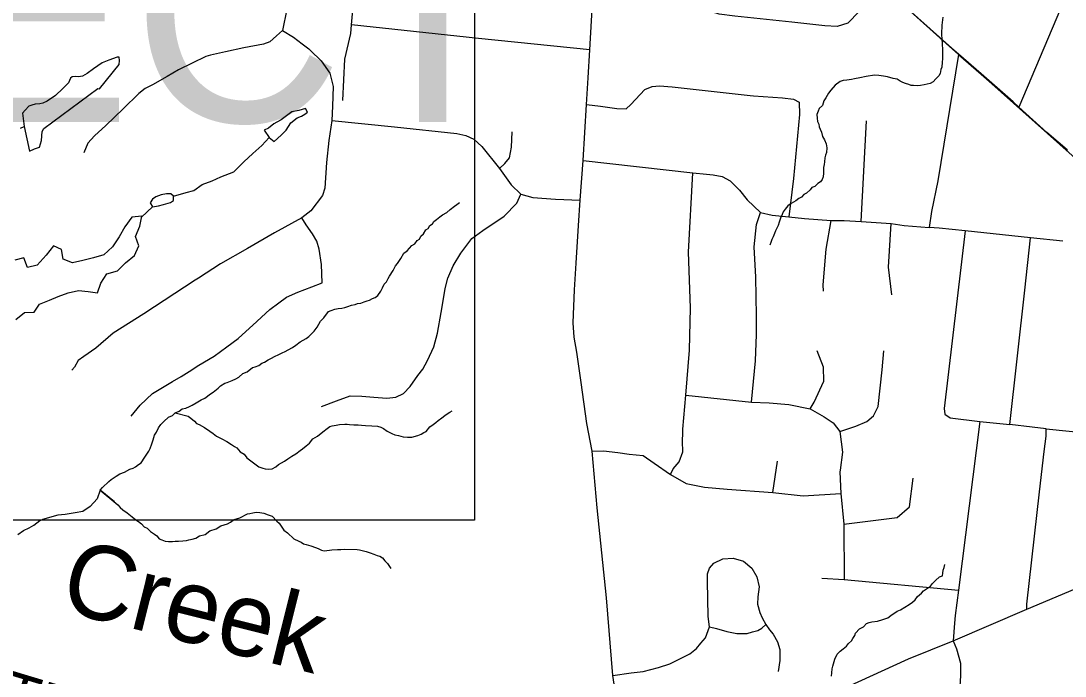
# Model space of a CAD drawing. Extents: x 0 to 34, y 0 to 22.
# Drawn here: x 6.811 to 7.478, y 14.523 to 14.941 of the extents above; entities that cross this region are included whole.
import ezdxf

# ---------------------------------------------------------------- set-up
doc = ezdxf.new("R2010")
doc.units = 0
for name, color, linetype in [('Default', 7, 'Continuous'), ('GM_X_Corporation', 7, 'Continuous'), ('GM_X_County_Road', 7, 'Continuous'), ('GM_X_County_Road_Text', 7, 'Continuous'), ('GM_X_Minor_Lake', 7, 'Continuous'), ('GM_X_Minor_River', 7, 'Continuous'), ('GM_X_Minor_River_Text', 7, 'Continuous'), ('GM_X_Rail_Line', 7, 'Continuous'), ('GM_X_State_Route', 7, 'Continuous'), ('GM_X_Township', 7, 'Continuous'), ('GM_X_Township_Road', 7, 'Continuous'), ('SH_Text', 7, 'Continuous')]:
    doc.layers.add(name, color=color, linetype=linetype)

msp = doc.modelspace()

# ---------------------------------------------------------------- linework, layer by layer
at = {"layer": 'Default'}
msp.add_lwpolyline([(5.72003, 15.05333), (7.10043, 15.05333), (7.10043, 14.62233), (5.72003, 14.62233)], close=True, dxfattribs=at)
at = {"layer": 'GM_X_Corporation'}
for points in [[(7.48543, 14.97447), (7.44826, 14.88634), (7.4662, 14.87017), (7.47922, 14.85892)], [(7.47922, 14.85892), (7.4662, 14.87017), (7.44826, 14.88634), (7.44459, 14.88965), (7.42409, 14.90759), (7.40961, 14.92024), (7.40377, 14.92534), (7.37674, 14.94955)]]:
    msp.add_lwpolyline(points, dxfattribs=at)
at = {"layer": 'GM_X_County_Road'}
for points in [[(7.16536, 14.7866), (7.16688, 14.81062), (7.16792, 14.82692), (7.16996, 14.85227), (7.17194, 14.88792), (7.17312, 14.90505), (7.17413, 14.92296), (7.17633, 14.9603), (7.17775, 14.9708), (7.17953, 14.98109), (7.1819, 14.98879), (7.1851, 15.0002), (7.19108, 15.01505), (7.20244, 15.04252)], [(7.19462, 14.47266), (7.19273, 14.49817), (7.18876, 14.52298), (7.18487, 14.57269), (7.17892, 14.63024), (7.17568, 14.66641), (7.17231, 14.68409), (7.16861, 14.71026), (7.16576, 14.7296), (7.1641, 14.73924), (7.16342, 14.74839), (7.16428, 14.76959), (7.16536, 14.7866)], [(7.19462, 14.47266), (7.20479, 14.48077), (7.21024, 14.48461), (7.21649, 14.48758), (7.22219, 14.4894), (7.24943, 14.49374), (7.26769, 14.49671), (7.30242, 14.50216), (7.31344, 14.50423), (7.32554, 14.50851), (7.34044, 14.51676), (7.3531, 14.52237), (7.37775, 14.53379), (7.4064, 14.5452), (7.45328, 14.56541), (7.48427, 14.57849), (7.58457, 14.59524), (7.64482, 14.60405), (7.73637, 14.61978), (7.74169, 14.62255)]]:
    msp.add_lwpolyline(points, dxfattribs=at)
at = {"layer": 'GM_X_Minor_Lake'}
for points in [[(6.8734, 14.91826), (6.87207, 14.91829), (6.8669, 14.9163), (6.8625, 14.91468), (6.85692, 14.9108), (6.85287, 14.90784), (6.84999, 14.906), (6.84751, 14.90567), (6.84562, 14.9059), (6.84334, 14.90575), (6.84237, 14.90482), (6.84098, 14.90181), (6.83749, 14.89827), (6.83265, 14.89381), (6.82745, 14.89011), (6.82458, 14.88884), (6.82267, 14.8885), (6.81982, 14.88818), (6.81753, 14.88765), (6.81562, 14.88693), (6.81329, 14.88432), (6.81154, 14.88245), (6.8128, 14.87393)], [(6.8128, 14.87393), (6.81619, 14.85823), (6.81925, 14.85968), (6.8225, 14.86076), (6.82372, 14.86492), (6.82422, 14.8708), (6.82521, 14.87268), (6.85971, 14.89821), (6.86084, 14.89799), (6.87349, 14.91351), (6.87354, 14.91617), (6.8734, 14.91826)], [(6.90809, 14.8294), (6.9163, 14.83171), (6.92107, 14.83294), (6.92647, 14.83682), (6.93278, 14.83917), (6.93834, 14.84172), (6.94676, 14.84497), (6.95296, 14.85131), (6.95876, 14.8567), (6.96456, 14.86171), (6.96922, 14.86694)], [(6.89466, 14.82264), (6.89847, 14.82332), (6.90172, 14.82402), (6.90611, 14.82526), (6.90803, 14.82655), (6.90809, 14.8294), (6.90641, 14.83096), (6.90375, 14.83082), (6.90032, 14.83032), (6.89688, 14.82906), (6.89476, 14.82739), (6.89319, 14.82514)], [(6.88775, 14.81594), (6.89466, 14.82264)], [(6.89319, 14.82514), (6.89467, 14.82264)], [(6.8074, 14.75066), (6.81281, 14.75511), (6.81908, 14.75537), (6.82241, 14.76043), (6.82891, 14.76296), (6.83447, 14.76532), (6.84078, 14.76766), (6.84745, 14.76905), (6.85352, 14.76855), (6.85958, 14.76767), (6.8616, 14.7739), (6.86552, 14.77971), (6.87239, 14.78166), (6.87743, 14.78669), (6.88322, 14.79152), (6.886, 14.79773), (6.88384, 14.80366), (6.88663, 14.81026), (6.8879, 14.8167), (6.88143, 14.81607), (6.87693, 14.8097), (6.87339, 14.8035), (6.86909, 14.79693), (6.86367, 14.79191), (6.85698, 14.78995), (6.85012, 14.78838), (6.84363, 14.7868), (6.8376, 14.7892), (6.83658, 14.7953), (6.8315, 14.79768), (6.82683, 14.7917), (6.821, 14.78535), (6.8149, 14.78376), (6.81255, 14.79008), (6.80682, 14.78849)]]:
    msp.add_lwpolyline(points, dxfattribs=at)
at = {"layer": 'GM_X_Minor_River'}
for points in [[(7.39965, 14.94389), (7.39899, 14.93877), (7.3989, 14.93307), (7.39902, 14.92926), (7.39937, 14.92736), (7.39948, 14.92222), (7.39944, 14.92032), (7.39958, 14.91709), (7.39935, 14.915), (7.39911, 14.91177), (7.39851, 14.91026), (7.3979, 14.9078), (7.39712, 14.90629), (7.39518, 14.90443), (7.39344, 14.90237), (7.39152, 14.90145), (7.38961, 14.90091), (7.38771, 14.90057), (7.38542, 14.90004), (7.3837, 14.89988), (7.38105, 14.90011), (7.37953, 14.90014), (7.37802, 14.90074), (7.37574, 14.90134), (7.37404, 14.90195), (7.37235, 14.90293), (7.37047, 14.9041), (7.368, 14.90452), (7.36441, 14.90573), (7.36176, 14.90615), (7.35872, 14.90659), (7.35606, 14.90663), (7.35073, 14.90578), (7.34672, 14.90509), (7.34329, 14.90438), (7.34138, 14.90404), (7.33833, 14.90352), (7.33605, 14.90337), (7.33414, 14.90264), (7.33087, 14.90042), (7.32815, 14.89705), (7.3266, 14.89517), (7.32503, 14.89216), (7.32366, 14.89028), (7.32286, 14.88744), (7.32073, 14.88539), (7.31994, 14.88369), (7.31914, 14.88161), (7.3193, 14.87933), (7.31964, 14.87704), (7.32037, 14.87532), (7.32072, 14.87379), (7.32127, 14.87226), (7.32219, 14.87034), (7.3229, 14.86748), (7.324, 14.86537), (7.3251, 14.86287), (7.32563, 14.8602), (7.32539, 14.85736), (7.32479, 14.85566)], [(6.96922, 14.86694), (6.9724, 14.86441), (6.97684, 14.86831), (6.98014, 14.87166), (6.98307, 14.87616), (6.98713, 14.8795), (6.98981, 14.88059), (6.99211, 14.88187), (6.99384, 14.88298), (6.99256, 14.88547), (6.98817, 14.88423), (6.98379, 14.88337), (6.97685, 14.87819), (6.97186, 14.87544)], [(6.81031, 14.87283), (6.8128, 14.87393)], [(6.97231, 14.87569), (6.96877, 14.87284), (6.96608, 14.87156), (6.96922, 14.86694)], [(7.32479, 14.85566), (7.32438, 14.85395), (7.32415, 14.85129), (7.32393, 14.84959), (7.32352, 14.84769), (7.32346, 14.84408), (7.32323, 14.8418), (7.32263, 14.8401), (7.32146, 14.8386), (7.31973, 14.83749), (7.31799, 14.83562), (7.31589, 14.8349), (7.31491, 14.83339), (7.3126, 14.83134), (7.31087, 14.83042), (7.30932, 14.82874), (7.30779, 14.828), (7.30567, 14.82652), (7.30279, 14.82467), (7.30067, 14.82318), (7.29893, 14.82112), (7.29776, 14.81943), (7.29697, 14.81773), (7.29598, 14.81528), (7.29518, 14.81282), (7.29438, 14.81074), (7.29359, 14.80886), (7.2928, 14.80716), (7.2922, 14.80546), (7.29122, 14.80338), (7.29043, 14.80169), (7.28983, 14.79979), (7.28923, 14.79809)], [(7.06926, 14.80784), (7.0708, 14.80876), (7.07197, 14.81064), (7.07351, 14.81176), (7.07449, 14.81326), (7.07622, 14.81456), (7.07834, 14.81624), (7.08007, 14.81754), (7.08276, 14.81901), (7.08488, 14.82088), (7.08758, 14.82311), (7.08912, 14.82403), (7.09085, 14.82533)], [(6.86117, 14.64147), (6.86272, 14.64316), (6.86677, 14.64708), (6.86832, 14.64838), (6.87158, 14.65042), (6.87389, 14.6519), (6.87676, 14.65299), (6.88021, 14.65483), (6.88231, 14.65555), (6.88385, 14.65648), (6.88578, 14.65797), (6.8875, 14.65889), (6.88985, 14.66265), (6.89238, 14.66641), (6.89317, 14.66811), (6.89417, 14.67113), (6.89516, 14.67359), (6.89597, 14.67661), (6.89734, 14.67868), (6.89852, 14.68132), (6.90008, 14.68339), (6.90202, 14.68545), (6.90491, 14.68825), (6.9074, 14.68916), (6.90914, 14.69103), (6.91182, 14.69193), (6.91375, 14.69342), (6.91604, 14.69395), (6.91833, 14.69505), (6.92006, 14.69578), (6.92255, 14.69726), (6.92582, 14.69929), (6.92812, 14.7002), (6.93177, 14.70299), (6.9335, 14.7041), (6.93659, 14.70671), (6.93814, 14.70821), (6.94082, 14.70987), (6.94236, 14.71041), (6.94561, 14.71169), (6.9479, 14.7126), (6.94982, 14.71371), (6.95234, 14.71613), (6.95521, 14.71723), (6.95867, 14.71983), (6.9602, 14.72037), (6.96269, 14.72128), (6.96461, 14.72277), (6.96633, 14.72331), (6.96864, 14.72479), (6.97037, 14.72571), (6.97305, 14.72718), (6.97497, 14.7281), (6.97746, 14.7292), (6.97956, 14.73011), (6.98148, 14.73122), (6.98417, 14.73269), (6.98629, 14.73418), (6.98898, 14.73622), (6.99282, 14.73844), (6.99455, 14.73974), (6.99803, 14.7431), (6.99998, 14.74573), (7.00213, 14.74949), (7.00426, 14.75155), (7.00718, 14.75568), (7.0089, 14.75641), (7.01119, 14.75713), (7.01329, 14.75766), (7.01558, 14.75781), (7.01768, 14.75835), (7.01959, 14.75889), (7.02188, 14.7598), (7.02417, 14.76014), (7.0257, 14.76087), (7.0278, 14.76102), (7.0299, 14.76194), (7.03181, 14.76248), (7.03334, 14.76302), (7.03526, 14.76394), (7.03698, 14.76467), (7.03872, 14.76597), (7.04066, 14.76879), (7.04165, 14.77086), (7.04283, 14.77312), (7.04418, 14.77462), (7.04536, 14.77669), (7.04614, 14.7782), (7.04849, 14.78196), (7.04987, 14.78498), (7.05123, 14.78647), (7.05337, 14.78967), (7.05533, 14.79287), (7.05745, 14.79454), (7.06035, 14.79791), (7.06227, 14.79902), (7.06383, 14.80109), (7.06537, 14.80201), (7.06616, 14.8039), (7.06789, 14.80539), (7.06926, 14.80784)], [(6.90914, 14.69103), (6.91747, 14.68879), (6.91916, 14.68743), (6.9216, 14.68568), (6.9229, 14.68413), (6.9246, 14.68353), (6.92799, 14.68157), (6.93138, 14.67923), (6.93344, 14.67767), (6.93569, 14.67611), (6.93909, 14.67434), (6.9421, 14.67257), (6.94511, 14.67062), (6.94718, 14.66944), (6.94868, 14.66847), (6.95073, 14.66596), (6.95318, 14.66458), (6.95504, 14.66208), (6.95673, 14.66091), (6.95842, 14.65955), (6.96086, 14.65779), (6.96274, 14.65643), (6.96519, 14.65563), (6.96671, 14.65522), (6.9688, 14.65499), (6.97108, 14.65514), (6.97357, 14.65643), (6.97531, 14.65792), (6.97914, 14.65995), (6.98107, 14.66143), (6.98376, 14.66329), (6.98626, 14.66477), (6.98895, 14.66681), (6.99049, 14.66793), (6.99281, 14.66979), (6.99493, 14.67146), (6.99706, 14.67428), (7.00014, 14.67612), (7.0036, 14.67873), (7.0063, 14.68096), (7.00803, 14.68226), (7.00956, 14.68262), (7.01204, 14.68314), (7.01414, 14.68349), (7.01756, 14.68362), (7.01908, 14.68359), (7.0206, 14.68356), (7.02326, 14.68333), (7.02611, 14.68328), (7.0282, 14.68305), (7.03085, 14.68281), (7.03484, 14.68255), (7.03845, 14.68249), (7.04053, 14.68169), (7.04223, 14.6809), (7.04467, 14.67915), (7.04769, 14.67777), (7.04957, 14.67697), (7.05184, 14.67636), (7.05487, 14.67555), (7.05772, 14.67531), (7.06038, 14.67545), (7.0642, 14.67652), (7.06631, 14.67725), (7.06804, 14.67836), (7.06957, 14.67909), (7.0719, 14.68191), (7.07402, 14.68358), (7.07575, 14.68469), (7.07729, 14.686), (7.0796, 14.68767), (7.08152, 14.68915), (7.08306, 14.69027), (7.0846, 14.69138), (7.08614, 14.69231)], [(6.86117, 14.64147), (6.85924, 14.63597), (6.85496, 14.63112), (6.85015, 14.62779), (6.8452, 14.62694), (6.83891, 14.62593), (6.83415, 14.62545), (6.82433, 14.62282)], [(6.87032, 14.63398), (6.86117, 14.64147), (6.87261, 14.63214), (6.8741, 14.6304), (6.87578, 14.62885), (6.87841, 14.6271), (6.88179, 14.62438), (6.88404, 14.62262), (6.88573, 14.62145), (6.88761, 14.62009), (6.88948, 14.61816), (6.89136, 14.61717), (6.89342, 14.61504), (6.89605, 14.61348), (6.89755, 14.61231), (6.89904, 14.61038), (6.90074, 14.60978), (6.90282, 14.60898), (6.90491, 14.60876), (6.90738, 14.60871), (6.90909, 14.60887), (6.91137, 14.60883), (6.91404, 14.60917), (6.91632, 14.60932), (6.91785, 14.60967), (6.91995, 14.61021), (6.92243, 14.61073), (6.92474, 14.6124), (6.92836, 14.6131), (6.93125, 14.61552), (6.93546, 14.61678), (6.93834, 14.61882), (6.94255, 14.62008), (6.94446, 14.621), (6.94696, 14.62266), (6.95059, 14.62374), (6.95539, 14.62632), (6.95691, 14.62667), (6.95882, 14.62702), (6.96092, 14.62736), (6.9632, 14.62732), (6.96585, 14.6269), (6.96868, 14.62571), (6.97114, 14.6249), (6.97413, 14.62162), (6.97563, 14.62045), (6.97859, 14.61603), (6.98104, 14.61427), (6.98496, 14.6104), (6.98817, 14.60901), (6.98968, 14.60822), (6.99118, 14.60725), (6.99289, 14.60684), (6.99591, 14.60602), (6.99875, 14.60483), (7.00064, 14.60423), (7.00271, 14.60324), (7.00441, 14.60283), (7.00784, 14.60315), (7.00937, 14.60332), (7.01298, 14.60363), (7.01507, 14.6036), (7.01717, 14.60375), (7.02553, 14.6036), (7.02705, 14.60339), (7.02951, 14.60277), (7.03121, 14.60236), (7.03385, 14.60137), (7.03612, 14.60057), (7.0382, 14.59977), (7.0399, 14.59936), (7.04159, 14.59819), (7.04308, 14.59626), (7.04477, 14.59471), (7.04699, 14.59144)], [(6.8159, 14.61749), (6.81878, 14.61913), (6.82265, 14.62207), (6.82433, 14.62282)], [(6.80858, 14.61312), (6.81225, 14.61569), (6.8159, 14.61749)], [(7.34221, 14.54671), (7.34339, 14.54859), (7.34398, 14.5501), (7.3465, 14.55291), (7.34899, 14.5542), (7.35093, 14.55626), (7.35265, 14.55699), (7.35437, 14.55734), (7.35799, 14.55785), (7.36143, 14.55893), (7.36448, 14.55982), (7.36641, 14.56131), (7.37045, 14.56429), (7.37256, 14.56501), (7.37544, 14.56667), (7.37813, 14.56852), (7.38024, 14.57001), (7.38198, 14.5715), (7.38354, 14.57357), (7.38604, 14.57561), (7.3874, 14.57711), (7.3899, 14.57897), (7.39182, 14.58008), (7.39318, 14.58176), (7.39492, 14.58383), (7.39762, 14.58606), (7.39954, 14.58679), (7.39975, 14.5885), (7.39998, 14.59039), (7.40057, 14.59209), (7.40099, 14.59399)], [(7.3285, 14.52261), (7.32873, 14.5247), (7.32896, 14.52736), (7.32937, 14.52906), (7.33077, 14.53341), (7.33216, 14.53681), (7.33409, 14.53868), (7.33602, 14.54016), (7.33814, 14.54184), (7.3395, 14.54353), (7.34143, 14.5452), (7.34221, 14.54671)]]:
    msp.add_lwpolyline(points, dxfattribs=at)
at = {"layer": 'GM_X_Rail_Line'}
msp.add_lwpolyline([(8.09411, 14.30513), (7.91188, 14.48462), (7.73883, 14.62661), (7.37583, 14.95031), (7.27768, 15.03727), (7.11629, 15.18835), (7.09242, 15.20728), (7.06464, 15.22387), (6.89163, 15.30383), (6.63068, 15.45516), (6.60772, 15.46474), (6.58368, 15.4712), (6.35418, 15.49636), (6.26415, 15.50162), (6.17974, 15.50653), (6.14837, 15.51701), (6.12521, 15.53414), (6.05954, 15.61782), (6.04079, 15.63718), (6.02351, 15.65035), (5.8776, 15.71198), (5.85703, 15.71911), (5.83342, 15.72349), (5.69367, 15.73607)], dxfattribs=at)
at = {"layer": 'GM_X_State_Route'}
msp.add_lwpolyline([(7.22137, 15.0883), (7.23452, 15.07553), (7.24293, 15.06788), (7.2606, 15.05198), (7.27671, 15.03694), (7.29503, 15.02089), (7.31432, 15.00393), (7.32877, 14.99105), (7.34589, 14.97629), (7.36121, 14.963), (7.37686, 14.94929), (7.40388, 14.92508), (7.40973, 14.91998), (7.4242, 14.90733), (7.44471, 14.88939), (7.44838, 14.88608), (7.46632, 14.8699), (7.47934, 14.85866)], dxfattribs=at)
at = {"layer": 'GM_X_Township'}
msp.add_lwpolyline([(7.48543, 14.97447), (7.44826, 14.88634), (7.44459, 14.88965), (7.42409, 14.90759), (7.40961, 14.92024), (7.40377, 14.92534), (7.37674, 14.94955)], dxfattribs=at)
at = {"layer": 'GM_X_Township_Road'}
for p, q in [((7.02141, 14.93326), (7.02178, 14.93886)), ((7.34743, 14.8133), (7.35082, 14.87764)), ((7.42333, 14.68529), (7.44242, 14.68348)), ((7.46579, 14.6807), (7.49934, 14.6773)), ((7.29107, 14.63992), (7.29414, 14.65997))]:
    msp.add_line(p, q, dxfattribs=at)
for points in [[(7.02178, 14.93886), (7.02443, 14.96676), (7.02465, 14.96905), (7.02795, 14.99713)], [(7.36121, 14.963), (7.33893, 14.93986), (7.33218, 14.93782), (7.32436, 14.93836), (7.30325, 14.94061), (7.26672, 14.94436), (7.25686, 14.94575), (7.25279, 14.94693), (7.24743, 14.94886), (7.23533, 14.95582), (7.22858, 14.96086), (7.22076, 14.96643), (7.20383, 14.96804), (7.17775, 14.9708)], [(6.98336, 14.96273), (6.97767, 14.93517), (6.97403, 14.93178), (6.96962, 14.92805), (6.96557, 14.92659), (6.95296, 14.92411), (6.94128, 14.92164), (6.93183, 14.91948), (6.92883, 14.91875), (6.91134, 14.91009), (6.90411, 14.90594), (6.89461, 14.90046), (6.89011, 14.89816), (6.88592, 14.89497), (6.87588, 14.8852), (6.86489, 14.87453), (6.85773, 14.86789), (6.85348, 14.8632), (6.8509, 14.85699)], [(6.97767, 14.93517), (6.98472, 14.93091), (6.99038, 14.92678), (6.99449, 14.92348)], [(7.01622, 14.8906), (7.0177, 14.91693), (7.02141, 14.93326)], [(7.17413, 14.92296), (7.10292, 14.9302), (7.02178, 14.93886)], [(6.99449, 14.92348), (6.99573, 14.9225), (7.0024, 14.91597), (7.00794, 14.90801), (7.01007, 14.89949), (7.00965, 14.88699), (7.00921, 14.87786), (7.00743, 14.86496), (7.00581, 14.85093), (7.00488, 14.83444), (7.00324, 14.82992), (6.99587, 14.82004), (6.99012, 14.81564), (6.97265, 14.80591), (6.95547, 14.79604), (6.93822, 14.78624), (6.92404, 14.77708), (6.92198, 14.77567), (6.88917, 14.75413), (6.86951, 14.74193), (6.85844, 14.73234), (6.85072, 14.72704), (6.84723, 14.72428), (6.84485, 14.72017), (6.84308, 14.71812)], [(7.40973, 14.91998), (7.39657, 14.83914), (7.39247, 14.81955), (7.391, 14.80942)], [(7.17194, 14.88792), (7.18094, 14.88682), (7.19143, 14.88549), (7.19743, 14.88516), (7.20043, 14.88799), (7.20925, 14.89748), (7.21392, 14.89948), (7.21875, 14.89981), (7.22674, 14.89931), (7.2766, 14.89372)], [(7.2766, 14.89372), (7.2787, 14.89348), (7.29718, 14.89232), (7.30434, 14.89148), (7.30784, 14.88949), (7.30817, 14.88149), (7.30499, 14.84758)], [(7.00921, 14.87786), (7.04925, 14.87362), (7.08923, 14.86948), (7.09498, 14.86825), (7.10012, 14.86592), (7.10517, 14.86108), (7.11634, 14.84714), (7.12389, 14.83674), (7.13001, 14.83063), (7.13777, 14.82855), (7.15225, 14.82749), (7.16792, 14.82692)], [(7.11634, 14.84714), (7.11992, 14.85022), (7.12291, 14.85396), (7.12399, 14.86061), (7.12457, 14.87043)], [(7.16996, 14.85227), (7.24002, 14.84439), (7.24863, 14.84351), (7.25303, 14.84299), (7.25866, 14.84193), (7.26376, 14.83912), (7.26974, 14.83331), (7.27467, 14.82698), (7.28311, 14.81889), (7.29067, 14.81731), (7.30122, 14.81625), (7.31125, 14.8152), (7.32837, 14.81393), (7.33656, 14.81393), (7.34743, 14.8133), (7.35704, 14.81267), (7.36664, 14.81189), (7.3749, 14.81072), (7.391, 14.80942)], [(7.30499, 14.84758), (7.30434, 14.84069), (7.30122, 14.81625)], [(7.23349, 14.67813), (7.23359, 14.68055), (7.23544, 14.70227), (7.2378, 14.73089), (7.23847, 14.75799), (7.23713, 14.79368), (7.24002, 14.84439)], [(7.00265, 14.69501), (7.01226, 14.69867), (7.02103, 14.70188), (7.02842, 14.70161), (7.03614, 14.7009), (7.04451, 14.70031), (7.05013, 14.70103), (7.05504, 14.70338), (7.05925, 14.7077), (7.06433, 14.71489), (7.06734, 14.71875), (7.07045, 14.72436), (7.07447, 14.73301), (7.07689, 14.74191), (7.07924, 14.75512), (7.08094, 14.76506), (7.08166, 14.77036), (7.08349, 14.7771), (7.08685, 14.78484), (7.09177, 14.79293), (7.09876, 14.80233), (7.10586, 14.80746), (7.11931, 14.81653), (7.12739, 14.82484), (7.13001, 14.83063)], [(6.88099, 14.68876), (6.88681, 14.69585), (6.89462, 14.70338), (6.9074, 14.71105), (6.91308, 14.71417), (6.91819, 14.71744), (6.9243, 14.72141), (6.9341, 14.7271), (6.94219, 14.73306), (6.94938, 14.73847), (6.95432, 14.74298), (6.95881, 14.74698), (6.96959, 14.75689), (6.97542, 14.76132), (6.98039, 14.76487), (6.98751, 14.76801), (6.99658, 14.77154), (7.00306, 14.774), (7.00277, 14.78568), (7.00123, 14.79551), (6.99964, 14.80055), (6.99684, 14.80534), (6.99289, 14.81117), (6.99012, 14.81564)], [(7.27736, 14.69772), (7.27989, 14.72407), (7.28073, 14.74099), (7.28065, 14.75286), (7.28029, 14.77774), (7.27924, 14.79708), (7.28064, 14.81133), (7.28311, 14.81889)], [(7.32342, 14.76872), (7.32319, 14.7728), (7.32506, 14.79554), (7.32837, 14.81393)], [(7.36705, 14.76642), (7.36507, 14.78401), (7.36664, 14.81189)], [(7.47632, 14.80067), (7.4558, 14.80283), (7.41392, 14.80723), (7.39725, 14.80898), (7.391, 14.80942)], [(7.41392, 14.80723), (7.40057, 14.69365), (7.40094, 14.69004), (7.40445, 14.68777), (7.42333, 14.68529), (7.40967, 14.57769), (7.40767, 14.56143)], [(7.45328, 14.56541), (7.45328, 14.5686), (7.46142, 14.64052), (7.46454, 14.66625), (7.46573, 14.67612), (7.46579, 14.6807), (7.45679, 14.68176), (7.44242, 14.68348), (7.45214, 14.76939), (7.4558, 14.80283)], [(7.315, 14.69345), (7.31753, 14.6978), (7.32366, 14.71119), (7.32349, 14.72011), (7.31945, 14.73055)], [(7.33398, 14.67897), (7.34403, 14.6824), (7.35111, 14.6855), (7.35548, 14.68897), (7.35834, 14.69503), (7.36103, 14.71843), (7.36204, 14.73055)], [(7.23544, 14.70227), (7.27736, 14.69772), (7.28864, 14.69722), (7.30127, 14.69621)], [(7.30127, 14.69621), (7.315, 14.69345), (7.32383, 14.68846), (7.32955, 14.68459), (7.33398, 14.67897), (7.33551, 14.66579), (7.3341, 14.65423)], [(7.22568, 14.65159), (7.22736, 14.65513), (7.23124, 14.65968), (7.23359, 14.66607), (7.23326, 14.67281), (7.23349, 14.67813)], [(7.17568, 14.66641), (7.18292, 14.66658), (7.19201, 14.66557), (7.19925, 14.66456), (7.20817, 14.66372), (7.21524, 14.65867), (7.22568, 14.65159), (7.23562, 14.64587), (7.2474, 14.64351), (7.26197, 14.6422), (7.29107, 14.63992), (7.31055, 14.63794), (7.33453, 14.63945)], [(7.3341, 14.65423), (7.33398, 14.65323), (7.33453, 14.63945), (7.33643, 14.61983), (7.33659, 14.58443)], [(7.33643, 14.61983), (7.37045, 14.62412), (7.37841, 14.63086), (7.38083, 14.64928)], [(7.18876, 14.52298), (7.2006, 14.52479), (7.20816, 14.52561), (7.21802, 14.52824), (7.22522, 14.53062), (7.23249, 14.53416), (7.23808, 14.53696), (7.24235, 14.54024), (7.24515, 14.5437), (7.24809, 14.54724), (7.2505, 14.55412), (7.24966, 14.56075), (7.24926, 14.58346), (7.24936, 14.58796), (7.25064, 14.59167), (7.25337, 14.59481), (7.25905, 14.59755), (7.26571, 14.59814), (7.27236, 14.59618), (7.27765, 14.59168), (7.28078, 14.5862), (7.28234, 14.57974), (7.28156, 14.57328), (7.28136, 14.56858), (7.28273, 14.56329), (7.28424, 14.55991), (7.2867, 14.55567), (7.289, 14.55233), (7.29134, 14.5494), (7.29408, 14.5445), (7.29545, 14.53961), (7.29545, 14.53257), (7.29448, 14.52571)], [(7.32234, 14.5852), (7.33659, 14.58443), (7.40967, 14.57769)], [(7.40767, 14.56143), (7.40706, 14.55655), (7.4064, 14.5452), (7.40839, 14.54015), (7.41091, 14.53096), (7.41091, 14.52639), (7.41091, 14.52284), (7.41056, 14.51629), (7.41048, 14.51376), (7.41015, 14.50932), (7.40989, 14.50489), (7.40973, 14.49812), (7.41654, 14.46861)], [(7.2505, 14.55412), (7.25517, 14.55307), (7.26158, 14.55126), (7.26816, 14.54994), (7.27473, 14.54994), (7.27802, 14.55093), (7.28147, 14.55192), (7.28411, 14.55323), (7.2867, 14.55567)]]:
    msp.add_lwpolyline(points, dxfattribs=at)

# ---------------------------------------------------------------- texts
at = {"layer": 'GM_X_County_Road_Text'}
msp.add_text('WHITE', height=0.028409, rotation=343.23961, dxfattribs=at).set_placement((6.72452, 14.5207))
at = {"layer": 'GM_X_Minor_River_Text'}
msp.add_text('Creek', height=0.047348, rotation=345.9993, dxfattribs=at).set_placement((6.83399, 14.56502))
at = {"layer": 'SH_Text'}
msp.add_text('END PROJECT', height=0.1399997, dxfattribs=at).set_placement((5.80995, 14.87687))

doc.saveas('drawing.dxf')
